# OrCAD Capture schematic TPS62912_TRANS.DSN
size D; title: TPS62912  3-V to 17-V, 2-A Low Noise and Low Ripple Buck; rev: 1.1; note: Datasheet: SLVSFP4B  EVM:SLVUBX2A
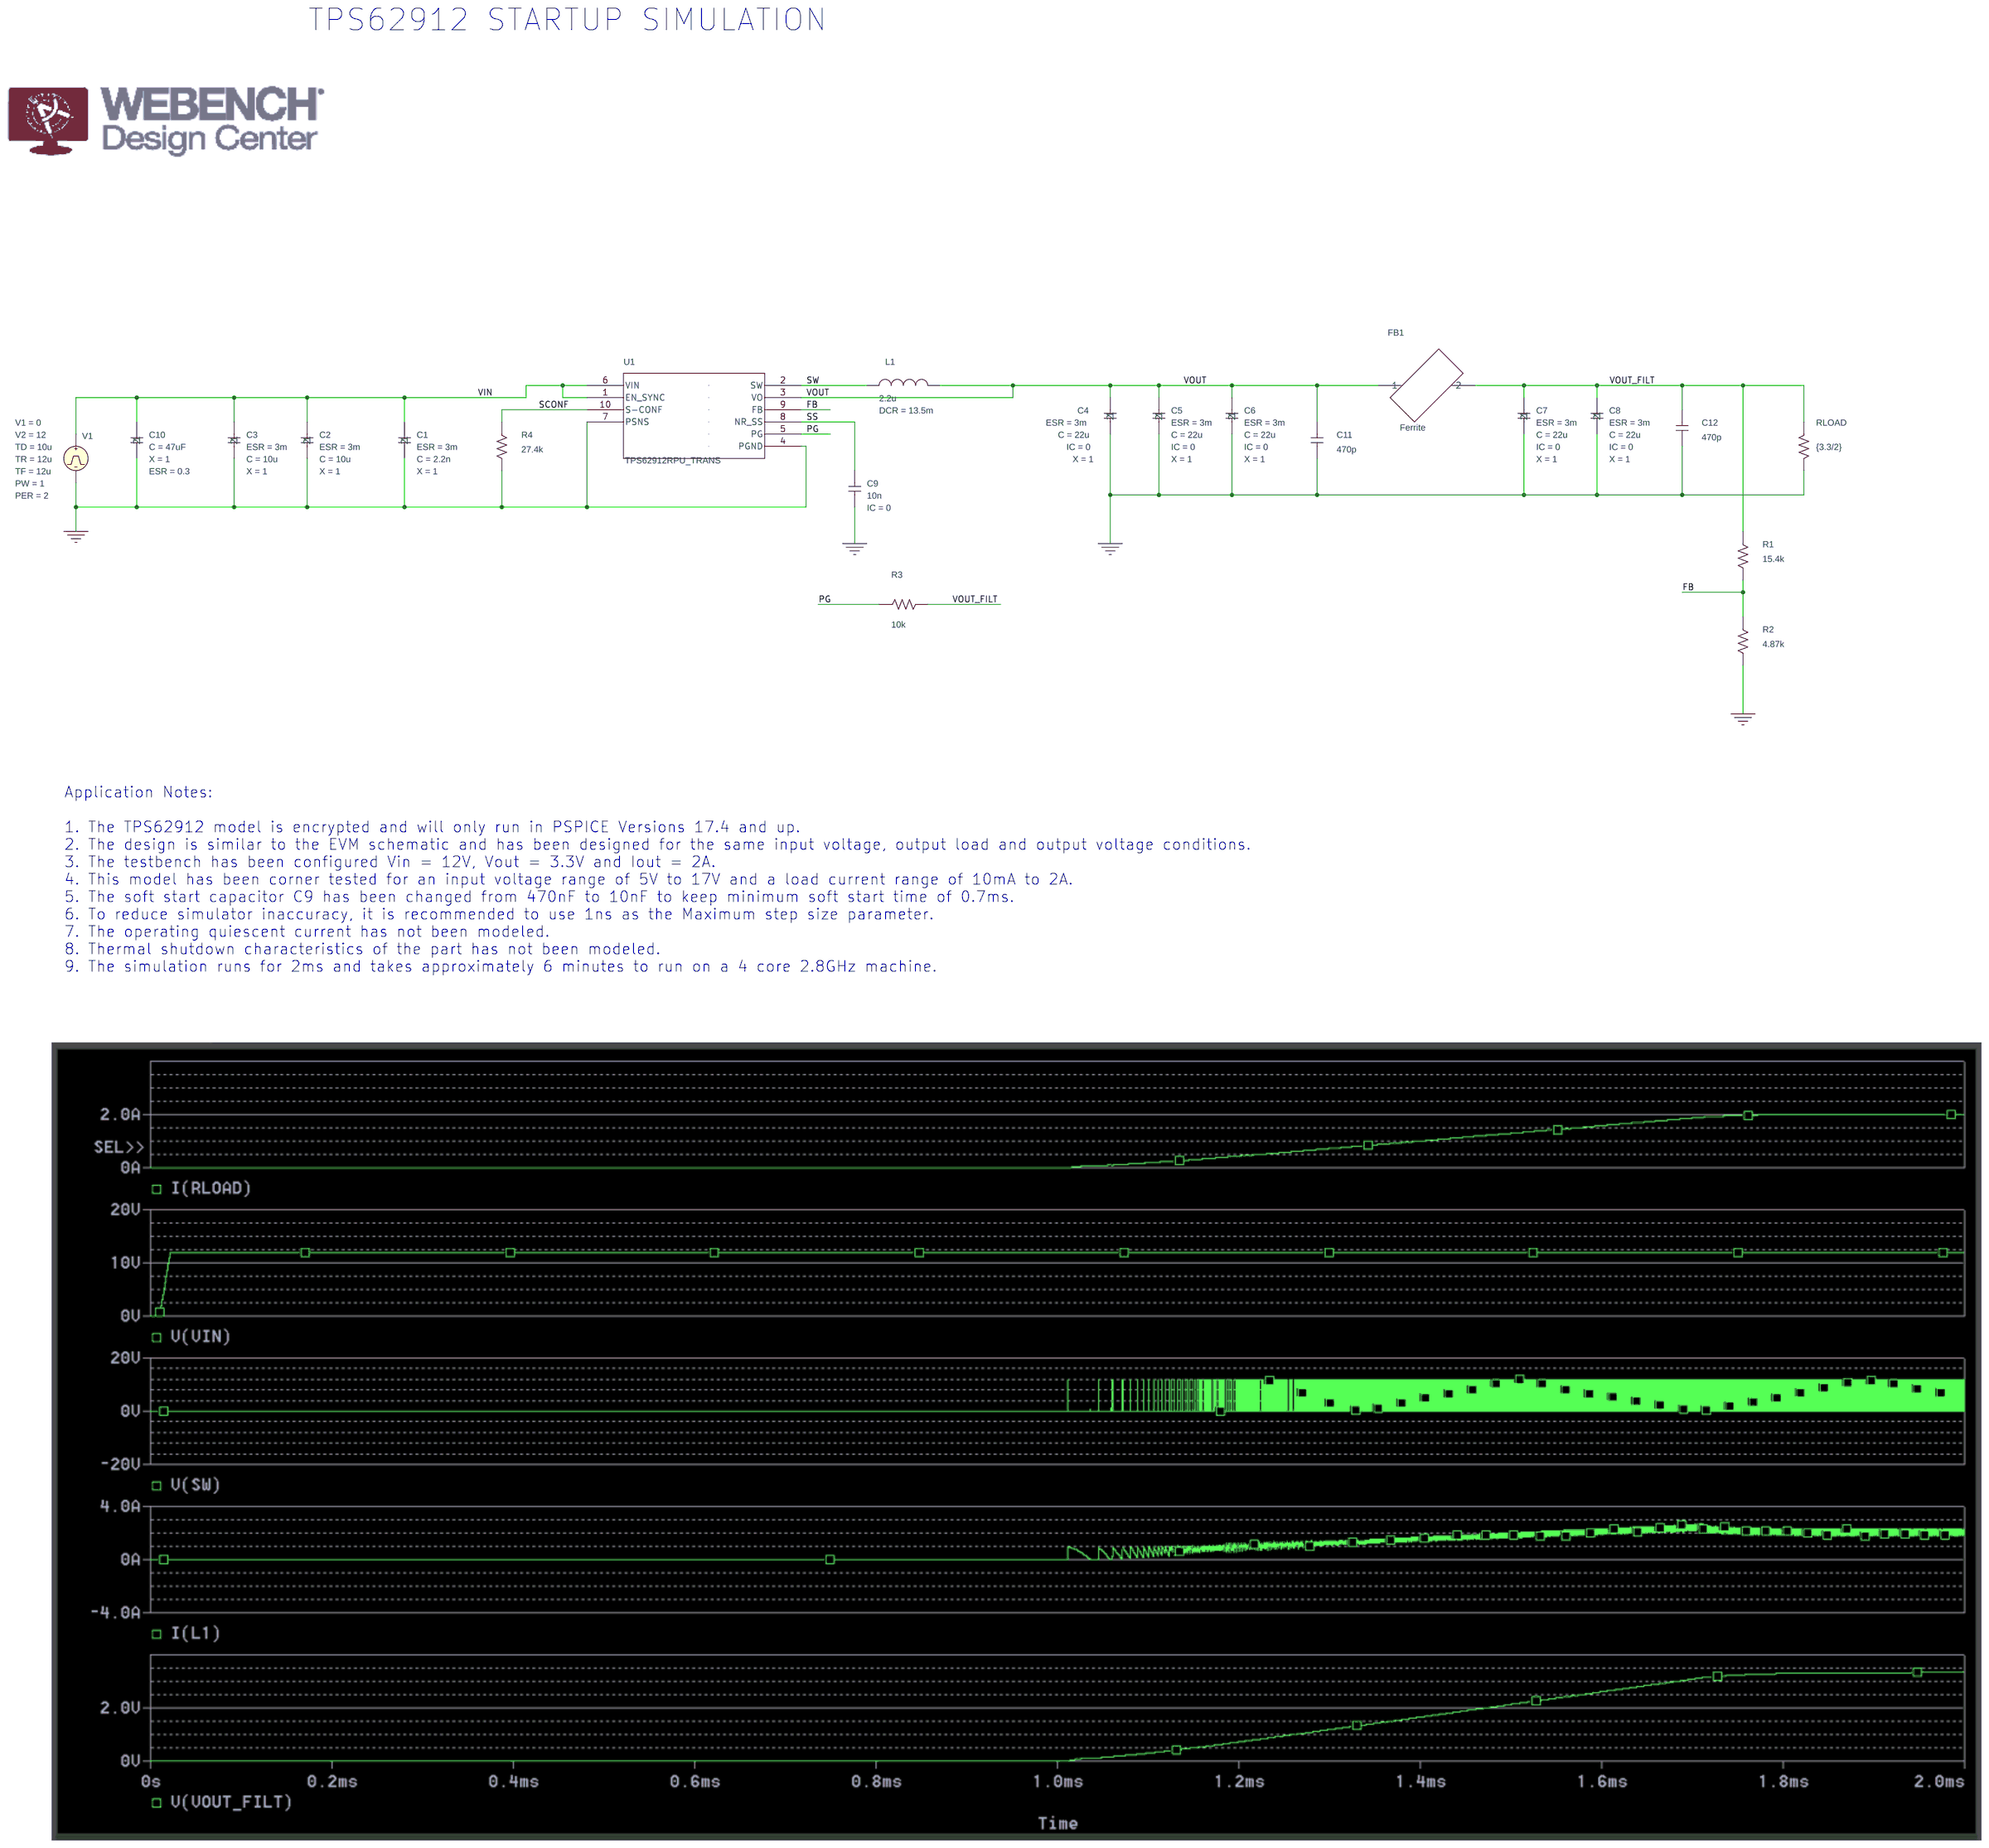
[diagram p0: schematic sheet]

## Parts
C1  CESR
C2  CESR
C3  CESR
C4  CESR
C5  CESR
C6  CESR
C7  CESR
C8  CESR
C9  10n  [RAD/CK05]
C10  CESR
C11  470p  [RAD/CK05]
C12  470p  [RAD/CK05]
FB1  Ferrite
L1  2.2u  [DISC/.350x.175/LS.200x.100/.034]
R1  15.4k  [AX/RC05]
R2  4.87k  [AX/RC05]
R3  10k  [AX/RC05]
R4  27.4k  [AX/RC05]
RLOAD  {3.3/2}  [AX/RC05]
U1  TPS62912RPU_TRANS  [RPU0010A-MFG]
V1  VPULSE

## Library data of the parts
C1 = CESR_1_1: C: 2.2n; ESR: 3m; PSpiceTemplate: X^@REFDES %1 %2 @MODEL PARAMS: ?C|C=@C||C=10U| ?ESR|ESR=@ESR||ESR=2M| ?IC|IC=@IC||IC=0| ?X|X=@X||X=0|; X: 1
C2 = CESR_1_6: C: 10u; ESR: 3m; PSpiceTemplate: X^@REFDES %1 %2 @MODEL PARAMS: ?C|C=@C||C=10U| ?ESR|ESR=@ESR||ESR=2M| ?IC|IC=@IC||IC=0| ?X|X=@X||X=0|; X: 1
C3 = CESR_1_7: C: 10u; ESR: 3m; PSpiceTemplate: X^@REFDES %1 %2 @MODEL PARAMS: ?C|C=@C||C=10U| ?ESR|ESR=@ESR||ESR=2M| ?IC|IC=@IC||IC=0| ?X|X=@X||X=0|; X: 1
C4 = CESR_1_2: C: 22u; ESR: 3m; IC: 0; PSpiceTemplate: X^@REFDES %1 %2 @MODEL PARAMS: ?C|C=@C||C=10U| ?ESR|ESR=@ESR||ESR=2M| ?IC|IC=@IC||IC=0| ?X|X=@X||X=0|; X: 1
C5 = CESR_1: C: 22u; ESR: 3m; IC: 0; PSpiceTemplate: X^@REFDES %1 %2 @MODEL PARAMS: ?C|C=@C||C=10U| ?ESR|ESR=@ESR||ESR=2M| ?IC|IC=@IC||IC=0| ?X|X=@X||X=0|; X: 1
C6 = CESR_1_4: C: 22u; ESR: 3m; IC: 0; PSpiceTemplate: X^@REFDES %1 %2 @MODEL PARAMS: ?C|C=@C||C=10U| ?ESR|ESR=@ESR||ESR=2M| ?IC|IC=@IC||IC=0| ?X|X=@X||X=0|; X: 1
C7 = CESR_1_5: C: 22u; ESR: 3m; IC: 0; PSpiceTemplate: X^@REFDES %1 %2 @MODEL PARAMS: ?C|C=@C||C=10U| ?ESR|ESR=@ESR||ESR=2M| ?IC|IC=@IC||IC=0| ?X|X=@X||X=0|; X: 1
C8 = CESR_1_3: C: 22u; ESR: 3m; IC: 0; PSpiceTemplate: X^@REFDES %1 %2 @MODEL PARAMS: ?C|C=@C||C=10U| ?ESR|ESR=@ESR||ESR=2M| ?IC|IC=@IC||IC=0| ?X|X=@X||X=0|; X: 1
C9 = C: IC: 0
C10 = CESR_1_8: C: 47uF; ESR: 0.3; PSpiceTemplate: X^@REFDES %1 %2 @MODEL PARAMS: ?C|C=@C||C=10U| ?ESR|ESR=@ESR||ESR=2M| ?IC|IC=@IC||IC=0| ?X|X=@X||X=0|; X: 1
C11 C12 = C
FB1 = Ferrite
L1 = L: DCR: 13.5m; IC: 0
R1-R4 RLOAD = R
U1 = TPS62912RPU_TRANS
V1 = VPULSE: PER: 2; PW: 1; TD: 10u; TF: 12u; TR: 12u; V1: 0; V2: 12

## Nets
VIN: C1.1 C2.1 C3.1 C10.1 U1.1(EN_SYNC) U1.6(VIN) V1.1(+)
0: C1.2 C2.2 C3.2 C4.2 C5.2 C6.2 C7.2 C8.2 C9.2 C10.2 C11.1 C12.1 R2.2 R4.2 RLOAD.2 U1.4(PGND) U1.7(PSNS) V1.2(-)
FB: R1.2 R2.1 U1.9(FB)
PG: R3.1 U1.5(PG)
SCONF: R4.1 U1.10(S-CONF)
SS: C9.1 U1.8(NR_SS)
SW: L1.1 U1.2(SW)
VOUT: C4.1 C5.1 C6.1 C11.2 FB1.1 L1.2 U1.3(VO)
VOUT_FILT: C7.1 C8.1 C12.2 FB1.2 R1.1 R3.2 RLOAD.1

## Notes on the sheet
- TPS62912 STARTUP SIMULATION
- Application Notes:
  1. The TPS62912 model is encrypted and will only run in PSPICE Versions 17.4 and up.
  2. The design is similar to the EVM schematic and has been designed for the same input voltage, output load and output voltage conditions.
  3. The testbench has been configured Vin = 12V, Vout = 3.3V and Iout = 2A.
  4. This model has been corner tested for an input voltage range of 5V to 17V and a load current range of 10mA to 2A.
  5. The soft start capacitor C9 has been changed from 470nF to 10nF to keep minimum soft start time of 0.7ms.
  6. To reduce simulator inaccuracy, it is recommended to use 1ns as the Maximum step size parameter.
  7. The operating quiescent current has not been modeled.
  8. Thermal shutdown characteristics of the part has not been modeled.
  9. The simulation runs for 2ms and takes approximately 6 minutes to run on a 4 core 2.8GHz machine.
